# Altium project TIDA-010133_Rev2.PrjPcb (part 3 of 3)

## Sheet 5_BUF802_PWR_PG1.SchDoc: 5_BUF802_PWR
size 431 x 279 mm; Date: Not shown in title block; ApprovedBy: Not shown in title block; CheckedBy: Not shown in title block; Author: Not shown in title block; CompanyName: Not shown in title block; DrawnBy: Rob Stoneham; Engineer: Not shown in title block; Organization: Not shown in title block; Address1: Not shown in title block; Address2: Not shown in title block; Address3: Not shown in title block; Address4: Not shown in title block; DocumentNumber: 6; Revision: Use project parameter SCH_Rev; SheetNumber: 6; SheetTotal: 8; PageSetup: Record=PageOptions¦CenterHorizontal=True¦CenterVertical=True¦PrintScale=1.00¦XCorrection=1.00¦YCorrection=1.00¦PrintKind=0¦BorderSize=5000000¦LeftOffset=0¦BottomOffset=0¦Orientation=2¦PaperLength=1000¦PaperWidth=1000¦Scale=100¦PaperSource=15¦PrintQuality=600¦MediaType=1¦DitherType=10¦PaperKind=Letter¦PrintScaleMode=1
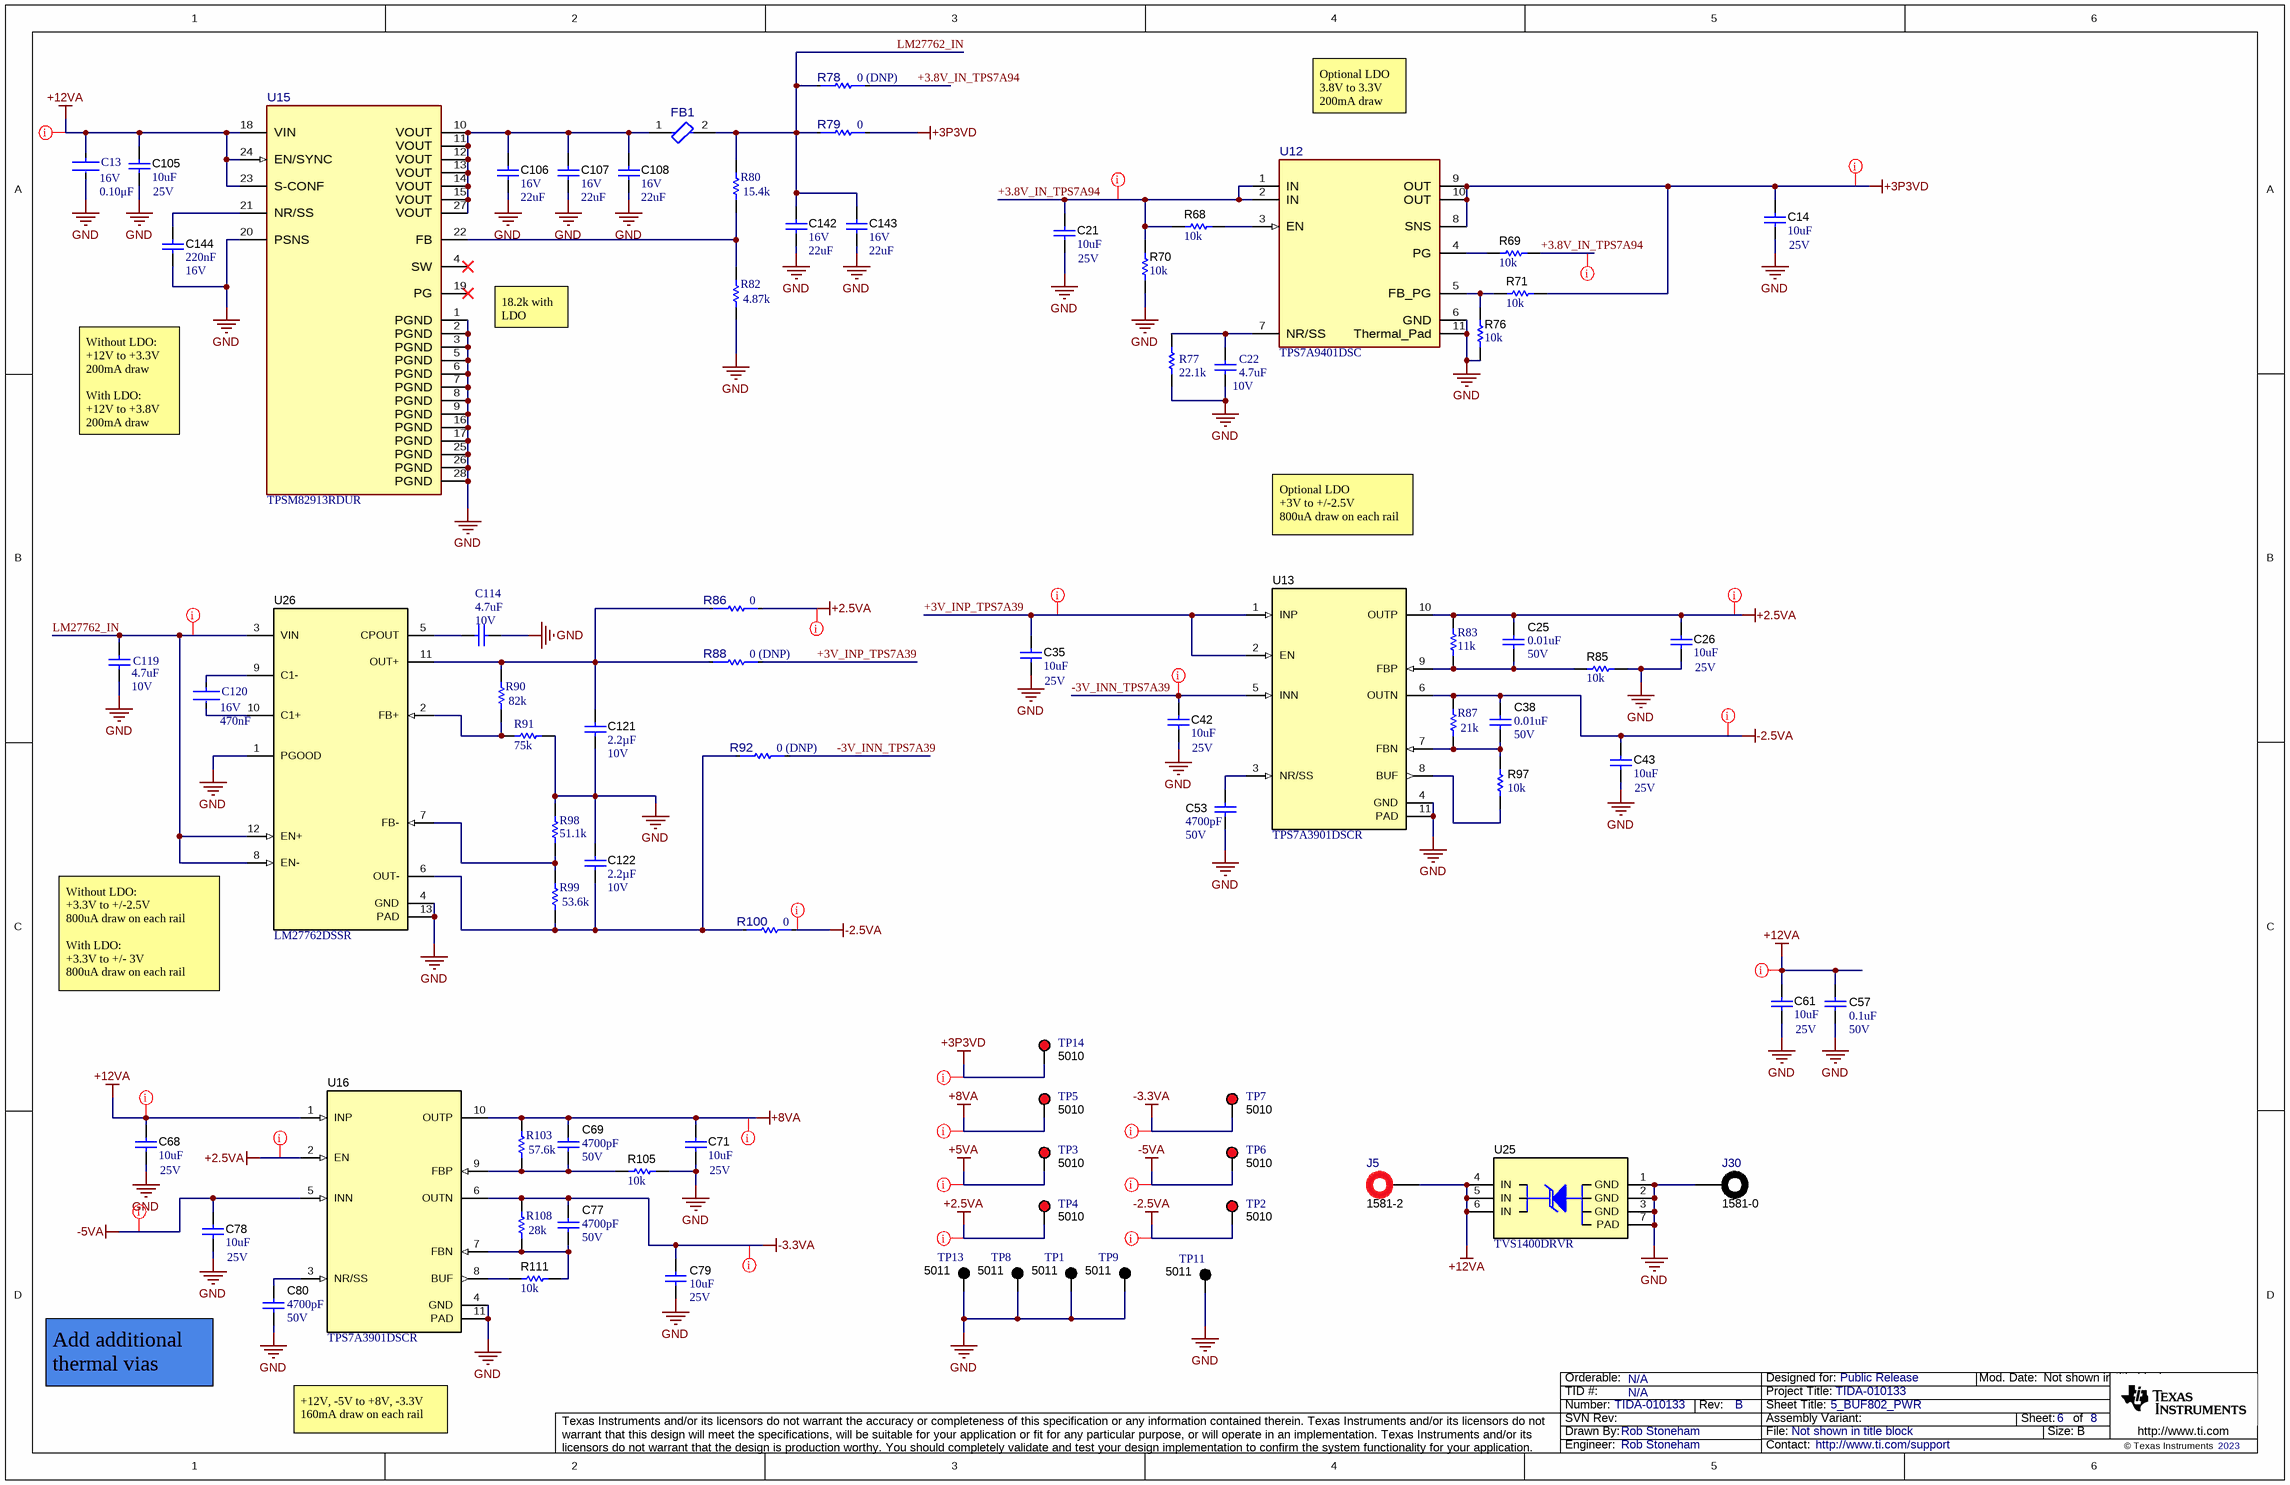
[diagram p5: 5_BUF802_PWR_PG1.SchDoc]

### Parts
C13  Voltage Rating: 16V  Capacitance: 0.10μF  [FP-GRM15-MFG]  (hidden comment: GRM155R71C104KA88D)
C14  ValueDisplayed: 10uF  Value2: 25V  [1206_190]  (hidden comment: C3216X7R1E106M160AE)
C21  ValueDisplayed: 10uF  Value2: 25V  [1206_190]  (hidden comment: C3216X7R1E106M160AE)
C22  value 4.7uF  Voltage Rating: 10V  [CAPC1608X87X35NL15T15]  (hidden comment: C0603C475K8PACTU)
C25  VDC_V: 50V  ValueDisplayed: 0.01uF  [0402]  (hidden comment: GRM155R71H103KA88D)
C26  ValueDisplayed: 10uF  Value2: 25V  [1206_190]  (hidden comment: C3216X7R1E106M160AE)
C35  ValueDisplayed: 10uF  Value2: 25V  [1206_190]  (hidden comment: C3216X7R1E106M160AE)
C38  VDC_V: 50V  ValueDisplayed: 0.01uF  [0402]  (hidden comment: GRM155R71H103KA88D)
C42  ValueDisplayed: 10uF  Value2: 25V  [1206_190]  (hidden comment: C3216X7R1E106M160AE)
C43  ValueDisplayed: 10uF  Value2: 25V  [1206_190]  (hidden comment: C3216X7R1E106M160AE)
C53  value 4700pF  VDC_V: 50V  [0603]  (hidden comment: 885012206087)
C57  ValueDisplayed: 0.1uF  Value2: 50V  [0603]  (hidden comment: CGA3E2X7R1H104K080AA)
C61  ValueDisplayed: 10uF  Value2: 25V  [1206_190]  (hidden comment: C3216X7R1E106M160AE)
C68  ValueDisplayed: 10uF  Value2: 25V  [1206_190]  (hidden comment: C3216X7R1E106M160AE)
C69  value 4700pF  VDC_V: 50V  [0603]  (hidden comment: 885012206087)
C71  ValueDisplayed: 10uF  Value2: 25V  [1206_190]  (hidden comment: C3216X7R1E106M160AE)
C77  value 4700pF  VDC_V: 50V  [0603]  (hidden comment: 885012206087)
C78  ValueDisplayed: 10uF  Value2: 25V  [1206_190]  (hidden comment: C3216X7R1E106M160AE)
C79  ValueDisplayed: 10uF  Value2: 25V  [1206_190]  (hidden comment: C3216X7R1E106M160AE)
C80  value 4700pF  VDC_V: 50V  [0603]  (hidden comment: 885012206087)
C105  ValueDisplayed: 10uF  Value2: 25V  [1206_190]  (hidden comment: C3216X7R1E106M160AE)
C106  VDC_V: 16V  ValueDisplayed: 22uF  [0805_HV]  (hidden comment: C2012X5R1C226K125AC)
C107  VDC_V: 16V  ValueDisplayed: 22uF  [0805_HV]  (hidden comment: C2012X5R1C226K125AC)
C108  VDC_V: 16V  ValueDisplayed: 22uF  [0805_HV]  (hidden comment: C2012X5R1C226K125AC)
C114  value 4.7uF  Voltage Rating: 10V  [CAPC1608X87X35NL15T15]  (hidden comment: C0603C475K8PACTU)
C119  value 4.7uF  Voltage Rating: 10V  [CAPC1608X87X35NL15T15]  (hidden comment: C0603C475K8PACTU)
C120  Voltage Rating (DC): 16V  Capacitance: 470nF  [FP-C1608-080-0_1-MFG]  (hidden comment: C1608X5R1C474K080AA)
C121  Cap_F: 2.2µF  VDC_V: 10V  [0603]  (hidden comment: C1608X7R1A225K080AC)
C122  Cap_F: 2.2µF  VDC_V: 10V  [0603]  (hidden comment: C1608X7R1A225K080AC)
C142  VDC_V: 16V  ValueDisplayed: 22uF  [0805_HV]  (hidden comment: C2012X5R1C226K125AC)
C143  VDC_V: 16V  ValueDisplayed: 22uF  [0805_HV]  (hidden comment: C2012X5R1C226K125AC)
C144  Cap_F: 220nF  VDC_V: 16V  [0603]  (hidden comment: GRM188R71C224KA01D)
FB1  BLE18PS080SN1D  [FP-BLE18PS080SN1D_0603-IPC_B]  (value not drawn)
J5  1581-2  [Pomona_1581-2]
J30  1581-0  [Pomona_1581-0]
R68  ValueDisplayed: 10k  [0603]  (hidden comment: CRCW060310K0JNEA)
R69  ValueDisplayed: 10k  [0603]  (hidden comment: CRCW060310K0JNEA)
R70  ValueDisplayed: 10k  [0603]  (hidden comment: CRCW060310K0JNEA)
R71  ValueDisplayed: 10k  [0603]  (hidden comment: CRCW060310K0JNEA)
R76  ValueDisplayed: 10k  [0603]  (hidden comment: CRCW060310K0JNEA)
R77  value 22.1k  [RESC1609X50X30LL10T20]  (hidden comment: CRCW060322K1FKEA)
R78  value 0 (DNP)  [FP-CRCW04020000Z0EDHP_0402-MFG]  (hidden comment: CRCW04020000Z0EDHP)
R79  value 0  [FP-CRCW04020000Z0EDHP_0402-MFG]  (hidden comment: CRCW04020000Z0EDHP)
R80  value 15.4k  [RESC1609X50X30LL10T20]  (hidden comment: CRCW060315K4FKEA)
R82  value 4.87k  [RESC1608X55X30ML15T15]  (hidden comment: ERJ-3EKF4871V)
R83  value 11k  [RESC1609X50X30ML10T20]  (hidden comment: CRCW060311K0FKEA)
R85  ValueDisplayed: 10k  [0603]  (hidden comment: CRCW060310K0JNEA)
R86  value 0  [FP-CRCW04020000Z0EDHP_0402-MFG]  (hidden comment: CRCW04020000Z0EDHP)
R87  value 21k  [RESC1609X50X30LL10T20]  (hidden comment: CRCW060321K0FKEA)
R88  value 0 (DNP)  [FP-CRCW04020000Z0EDHP_0402-MFG]  (hidden comment: CRCW04020000Z0EDHP)
R90  value 82k  [RESC1608X55X30LL15T15]  (hidden comment: ERJ3EKF8202V)
R91  value 75k  [RESC1609X50X30NL10T20]  (hidden comment: CRCW060375K0FKEA)
R92  value 0 (DNP)  [FP-CRCW04020000Z0EDHP_0402-MFG]  (hidden comment: CRCW04020000Z0EDHP)
R97  ValueDisplayed: 10k  [0603]  (hidden comment: CRCW060310K0JNEA)
R98  value 51.1k  [RESC1609X50X30ML10T20]  (hidden comment: CRCW060351K1FKEA)
R99  value 53.6k  [RESC1608X55X30NL15T15]  (hidden comment: ERJ-3EKF5362V)
R100  value 0  [FP-CRCW04020000Z0EDHP_0402-MFG]  (hidden comment: CRCW04020000Z0EDHP)
R103  value 57.6k  [RESC1608X55X30ML15T15]  (hidden comment: ERJ-3EKF5762V)
R105  ValueDisplayed: 10k  [0603]  (hidden comment: CRCW060310K0JNEA)
R108  value 28k  [RESC1608X55X30LL15T15]  (hidden comment: ERJ-3EKF2802V)
R111  ValueDisplayed: 10k  [0603]  (hidden comment: CRCW060310K0JNEA)
TP1  5011  [Keystone5011]
TP2  5010  [Keystone5010]
TP3  5010  [Keystone5010]
TP4  5010  [Keystone5010]
TP5  5010  [Keystone5010]
TP6  5010  [Keystone5010]
TP7  5010  [Keystone5010]
TP8  5011  [Keystone5011]
TP9  5011  [Keystone5011]
TP11  5011  [Keystone5011]
TP13  5011  [Keystone5011]
TP14  5010  [Keystone5010]
U12  TPS7A9401DSC  [DSC0010J-MFG]
U13  TPS7A3901DSCR  [DSC0010J]
U15  TPSM82913RDUR  [RDU0028A-MFG]
U16  TPS7A3901DSCR  [DSC0010J]
U25  TVS1400DRVR  [DRV0006A]
U26  LM27762DSSR  [DSS0012B]

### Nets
+2.5VA: C25.1 C26.1 R83.2 R86.2 TP4.1 U13.10(OUTP) U16.2(EN)
+3P3VD: C14.1 R71.1 R79.2 TP14.1 U12.8(SNS) U12.9(OUT) U12.10(OUT)
+5VA: TP3.1
+8VA: C69.1 C71.1 R103.2 TP5.1 U16.10(OUTP)
+12VA: C13.2 C57.1 C61.1 C68.1 C105.1 J5.1 U15.18(VIN) U15.23(S-CONF) U15.24(EN/SYNC) U16.1(INP) U25.4(IN) U25.5(IN) U25.6(IN)
-2.5VA: C38.1 C43.1 R87.2 R100.2 TP2.1 U13.6(OUTN)
-3.3VA: C77.1 C79.1 R108.2 TP7.1 U16.6(OUTN)
-5VA: C78.1 TP6.1 U16.5(INN)
GND: C13.1 C14.2 C21.2 C22.1 C26.2 C35.2 C42.2 C43.2 C53.2 C57.2 C61.2 C68.2 C71.2 C78.2 C79.2 C80.2 C105.2 C106.2 C107.2 C108.2 C114.1 C119.1 C121.2 C122.1 C142.2 C143.2 C144.2 J30.1 R70.1 R76.1 R77.1 R82.1 R85.1 R91.1 R98.2 R105.1 TP1.1 TP8.1 TP9.1 TP11.1 TP13.1 U12.6(GND) U12.11(Thermal_Pad) U13.4(GND) U13.11(PAD) U15.1(PGND) U15.2(PGND) U15.3(PGND) U15.5(PGND) U15.6(PGND) U15.7(PGND) U15.8(PGND) U15.9(PGND) U15.16(PGND) U15.17(PGND) U15.20(PSNS) U15.25(PGND) U15.26(PGND) U15.28(PGND) U16.4(GND) U16.11(PAD) U25.1(GND) U25.2(GND) U25.3(GND) U25.7(PAD) U26.1(PGOOD) U26.4(GND) U26.13(PAD)
+3.8V_IN_TPS7A94: C21.1 R68.1 R69.1 R70.2 R78.2 U12.1(IN) U12.2(IN)
+3V_INP_TPS7A39: C35.1 R88.2 U13.1(INP) U13.2(EN)
-3V_INN_TPS7A39: C42.1 R92.2 U13.5(INN)
LM27762_IN: C119.2 C142.1 C143.1 FB1.2 R78.1 R79.1 R80.2 U26.3(VIN) U26.8(EN-) U26.12(EN+)
NetC22_2: C22.2 R77.2 U12.7(NR/SS)
NetC25_2: C25.2 R83.1 R85.2 U13.9(FBP)
NetC38_2: C38.2 R87.1 R97.2 U13.7(FBN)
NetC53_1: C53.1 U13.3(NR/SS)
NetC69_2: C69.2 R103.1 R105.2 U16.9(FBP)
NetC77_2: C77.2 R108.1 R111.1 U16.7(FBN)
NetC80_1: C80.1 U16.3(NR/SS)
NetC106_1: C106.1 C107.1 C108.1 FB1.1 U15.10(VOUT) U15.11(VOUT) U15.12(VOUT) U15.13(VOUT) U15.14(VOUT) U15.15(VOUT) U15.27(VOUT)
NetC114_2: C114.2 U26.5(CPOUT)
NetC120_1: C120.1 U26.10(C1+)
NetC120_2: C120.2 U26.9(C1-)
NetC121_1: C121.1 R86.1 R88.1 R90.2 U26.11(OUT+)
NetC122_2: C122.2 R92.1 R99.1 R100.1 U26.6(OUT-)
NetC144_1: C144.1 U15.21(NR/SS)
NetR68_2: R68.2 U12.3(EN)
NetR69_2: R69.2 U12.4(PG)
NetR71_2: R71.2 R76.2 U12.5(FB_PG)
NetR80_1: R80.1 R82.2 U15.22(FB)
NetR90_1: R90.1 R91.2 U26.2(FB+)
NetR97_1: R97.1 U13.8(BUF)
NetR98_1: R98.1 R99.2 U26.7(FB-)
NetR111_2: R111.2 U16.8(BUF)

Not connected (* = marked no-connect by the designer): U15 4(SW)* 19(PG)*

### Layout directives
net class Power: +2.5VA, +3.8V_IN_TPS7A94, +3P3VD, +3V_INP_TPS7A39, +5VA, +8VA, +12VA, -2.5VA, -3.3VA, -3V_INN_TPS7A39, -5VA, LM27762_IN

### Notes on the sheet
- Optional LDO
  3.8V to 3.3V
  200mA draw
- 18.2k with LDO
- Without LDO:
  +12V to +3.3V
  200mA draw
  With LDO:
  +12V to +3.8V
  200mA draw
- Optional LDO
  +3V to +/-2.5V
  800uA draw on each rail
- Without LDO:
  +3.3V to +/-2.5V
  800uA draw on each rail
  With LDO:
  +3.3V to +/- 3V
  800uA draw on each rail
- Add additional thermal vias
- +12V, -5V to +8V, -3.3V
  160mA draw on each rail

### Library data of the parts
C13 = CMP-2100-03641-2: CAP CER 0.1UF 16V X7R 0402; Manufacturer: Murata; Standoff Height: 0mm; Tolerance: 10%; Material: Ceramic; Value: 0.10μF
C14 C21 C26 C35 C42 C43 C61 C68 C71 C78 C79 C105 = CMP-0008692-2: CAP, CERM, 10 uF, 25 V, +/- 20%, X7R, 1206_190; Manufacturer: TDK; Polarized: N; Value: 10uF; U/M: EA; Cap_F: 10µF; Value1: Unknown; TaMin_C: -55°C; TaMax_C: 125°C; Cap_Case: 1206; SizeArea_mm2: 5.12; SizeAreaWB_mm2: 10.92; SizeX_mm: 3.2; SizeY_mm: 1.6; SizeZ_mm: 1.9; AEC Category: Q200
C22 C114 C119 = CMP-2006-03238-1: CAP, CERM, 4.7uF, 10V, +/-10%, X5R, 0603; Manufacturer: Kemet
C25 C38 = CMP-0006674-2: CAP, CERM, 0.01 uF, 50 V, +/- 10%, X7R, 0402; Manufacturer: MuRata; TaMin_C: -55°C; Polarized: N; SizeAreaWB_mm2: 3; Value1: Unknown; U/M: EA; Value: 0.01uF; TaMax_C: 125°C; SizeZ_mm: 0.6; SizeX_mm: 1; SizeY_mm: 0.5; Cap_F: 10nF; AEC Category: Q200
C53 C69 C77 C80 = CMP-0006835-4: CAP, CERM, 4700 pF, 50 V, +/- 10%, X7R, 0603; Manufacturer: Wurth Elektronik; TaMin_C: -55°C; Polarized: N; SizeAreaWB_mm2: 4.68; Value1: Unknown; U/M: EA; TaMax_C: 125°C; SizeZ_mm: 1; SizeX_mm: 1.6; SizeY_mm: 0.8; SizeArea_mm2: 1.28; Cap_F: 4.7nF; AEC Category: Q200
C57 = CMP-0007078-4: CAP, CERM, 0.1 uF, 50 V, +/- 10%, X7R, AEC-Q200 Grade 1, 0603; Manufacturer: TDK; Polarized: N; Value: 0.1uF; U/M: EA; Cap_F: 100nF; ESR_ohm: 29.6m; Value1: 0.0296 ohm; IRMS_A: 971.99mA; TaMin_C: -55°C; TaMax_C: 125°C; SizeArea_mm2: 1.28; SizeAreaWB_mm2: 4.68; SizeX_mm: 1.6; SizeY_mm: 0.8; SizeZ_mm: 1; AEC Category: Q200; AEC Qualified: Y
C106-C108 C142 C143 = CMP-0007826-2: CAP, CERM, 22 uF, 16 V, +/- 10%, X5R, 0805; Manufacturer: TDK; TaMin_C: -55°C; Polarized: N; SizeAreaWB_mm2: 6.75; Value1: Unknown; U/M: EA; Value: 22uF; TaMax_C: 85°C; SizeZ_mm: 1.45; SizeX_mm: 2; SizeY_mm: 1.25; Cap_Case: 0805; SizeArea_mm2: 2.5; Cap_F: 22µF; AEC Category: Q200
C120 = CMP-08246-005464-1: Multilayer Ceramic Capacitors 470nF ±10% 16V X5R SMD 0603
C121 C122 = CMP-0007036-4: CAP, CERM, 2.2 uF, 10 V, +/- 10%, X7R, 0603; Manufacturer: TDK; TaMin_C: -55°C; ESR_ohm: 4.058m; Polarized: N; SizeAreaWB_mm2: 4.68; Value1: 0.004058 ohm; U/M: EA; Value: 2.2uF; TaMax_C: 125°C; SizeZ_mm: 1; SizeX_mm: 1.6; SizeY_mm: 0.8; SizeArea_mm2: 1.28; IRMS_A: 2.5827A; AEC Category: Q200
C144 = CMP-0007389-4: CAP, CERM, 0.22 uF, 16 V, +/- 10%, X7R, 0603; Manufacturer: MuRata; TaMin_C: -55°C; Polarized: N; SizeAreaWB_mm2: 4.68; Value1: Unknown; U/M: EA; Value: 0.22uF; TaMax_C: 125°C; SizeZ_mm: 1; SizeX_mm: 1.6; SizeY_mm: 0.8; SizeArea_mm2: 1.28; AEC Category: Q200
FB1 = CMP-0096943-2: Ferrite Chip Bead 8A 8.5Ohm 2-Pin 0603 Paper T/R; Manufacturer: Murata; AEC Qualified: No; Impedance At Frequency: 8.5Ω @ 100MHz; DCR_ohm: 4m; Test Frequency: 100MHz; Tolerance_%: 25%; SizeZ_mm: 0.75mm
J5 = CMP-0082515-1: Banana Jack Red, TH; Manufacturer: Pomona Electronics; ContactFinish: Tin; Gender: Female; Current_A: 15A
J30 = CMP-0082516-1: Banana Jack Black, TH; Manufacturer: Pomona Electronics; Gender: Female; Current_A: 15A; ContactFinish: Tin
R68-R71 R76 R85 R97 R105 R111 = CMP-0025701-4: RES, 10 k, 5%, 0.1 W, AEC-Q200 Grade 0, 0603; Manufacturer: Vishay-Dale; Value: 10k; Value_Code: 10k0; Power_W: 100mW; Value2: 0.1W; VDC_V: 75V; TempCo: 200 ppm/C; SizeArea_mm2: 1.28; SizeX_mm: 1.6; SizeY_mm: 0.8; SizeZ_mm: 1; EIA_Code: E24; AEC Category: Q200; AEC Qualified: Y; AEC Grade: 0
R77 = CMP-2000-03094-1: RES 22.1K, 1%, 0.1W, 0603; Manufacturer: Vishay Dale
R78 R88 R92 = CMP-0001606-2: RES Thick Film, 0Ω, 0.2W, 0402; Manufacturer: Vishay Dale; AEC Qualified: Yes; Res_ohm: 0; SizeZ_mm: 0.4mm; AEC Grade: Grade 0; Power_W: 200mW; VDC_V: 50V
R79 R86 R100 = CMP-0001606-2: RES Thick Film, 0Ω, 0.2W, 0402; Manufacturer: Vishay Dale; AEC Qualified: Yes; SizeZ_mm: 0.4mm; AEC Grade: Grade 0; Power_W: 200mW; VDC_V: 50V
R80 = CMP-2000-02924-1: RES 15.4K, 1%, 0.1W, 0603; Manufacturer: Vishay Dale
R82 = CMP-2000-00532-1: RES, 4.87k, 1%, 0.1W, 0603; Manufacturer: Panasonic
R83 = CMP-2000-03860-1: RES 11k, 1%, 0.1W, 0603; Manufacturer: Vishay Dale
R87 = CMP-2000-03080-1: RES 21k, 1%, 0.1W, 0603; Manufacturer: Vishay Dale
R90 = CMP-2000-00656-1: RES 82k, 1%, 0.1W, 0603; Manufacturer: Panasonic
R91 = CMP-2000-03571-1: RES 75k, 1%, 0.1W, 0603; Manufacturer: Vishay Dale
R98 = CMP-2000-03445-1: 51.1 kOhms ±1% 0.1W, 1/10W Chip Resistor 0603 (1608 Metric) Automotive AEC-Q200 Thick Film; Manufacturer: Vishay Dale
R99 = CMP-2000-00556-1: 53.6 kOhms ±1% 0.1W, 1/10W Chip Resistor 0603 (1608 Metric) Automotive AEC-Q200 Thick Film; Manufacturer: Panasonic
R103 = CMP-2000-00576-1: 57.6 kOhms ±1% 0.1W, 1/10W Chip Resistor 0603 (1608 Metric) Automotive AEC-Q200 Thick Film; Manufacturer: Panasonic
R108 = CMP-1012-00672-2: 28 kOhms ±1% 0.1W, 1/10W Chip Resistor 0603 (1608 Metric) Automotive AEC-Q200 Thick Film; Manufacturer: Panasonic
TP1 TP8 TP9 TP11 TP13 = CMP-0055148-2: Test Point, Multipurpose, Black, TH; Manufacturer: Keystone Electronics; CNHeader: FALSE; Green_Lifecycle: Active; Green_REACh: Passed; ContactFinish: Silver; CT: TRUE
TP2-TP7 TP14 = CMP-0055147-2: Test Point, Multipurpose, Red, TH; Manufacturer: Keystone Electronics; CNHeader: FALSE; Green_Lifecycle: Active; Green_REACh: Passed; ContactFinish: Silver; CT: TRUE
U12 = CMP-0091022-1: 1-A, Ultra-Low Noise, Ultra-High PSRR, RF Voltage Regulator; Manufacturer: Texas Instruments; Max Supply Voltage: 5.5V; Accuracy Percentage: 1-1.5%; SizeZ_mm: 0.8mm; Output Type: AdjustableProgrammable; Min Supply Voltage: 1.7V; TJmax_C: +150°C; Dropout Voltage: 210mV; AEC Qualified: No; Standoff Height: 0mm; Output Voltage: 0.4-5.3V; Number Of Outputs: 1; Nominal Supply Current: 15-47mA
U13 U16 = CMP-0013435-7: Dual, 150mA, Wide-Vin, Positive and Negative Low-Dropout (LDO) Voltage Regulator, DSC0010J (WSON-10); Alternate Manufacturer: Texas Instruments; Alternate PartNumber: TPS7A3901DSCT; Rating: Catalog; CompType: IC; SizeAreaWB_mm2: 16.0; SizeY_mm: 3.0; AEC Qualified: N; SizeZ_mm: 0.8; SizeArea_mm2: 9.0; AEC Category: Q200
U15 = CMP-0094707-3: 3-V to 17-V, 3-A Low Noise and Low Ripple Buck Converter Module with Integrated Ferrite Bead Filter Compensation; Manufacturer: Texas Instruments; Switching Frequency: 1/2.2MHz; Max Duty Cycle: 100%; Output Voltage: 0.8-5.5V; Standoff Height: 0mm; CompType: IC; Number Of Outputs: 1; Max Supply Voltage: 17V; AEC Category: Q200; TJmax_C: +125°C; Nominal Supply Current: 5mA; SizeZ_mm: 1.9mm; Output Type: AdjustableProgrammable; Min Supply Voltage: 3V; AEC Qualified: No
U25 = CMP-0077836-1: 14-V Precision Surge Protection Clamp, DRV0006A (WSON-6); Alternate Manufacturer: Texas Instruments; SizeAreaWB_mm2: 9.0; SizeZ_mm: 0.8; SizeX_mm: 2.0; SizeArea_mm2: 4.0; CompType: IC; AEC Qualified: N; AEC Category: Q200
U26 = CMP-0076280-3: Low-Noise Positive- and Negative-Output Charge Pump With Integrated LDO, DSS0012B (WSON-12); Alternate PartNumber: LM27762DSST; Alternate Manufacturer: Texas Instruments; SizeZ_mm: 0.8; SizeArea_mm2: 6.0; AEC Qualified: N; Rating: Catalog; SizeY_mm: 3.0; SizeX_mm: 2.0; CompType: IC; AEC Category: Q200; SizeAreaWB_mm2: 12.0

## Sheet 6_BUF802_PWR_PG2.SchDoc
size 431 x 279 mm; Date: Not shown in title block; ApprovedBy: Not shown in title block; CheckedBy: Not shown in title block; Author: Not shown in title block; CompanyName: Not shown in title block; Engineer: Not shown in title block; Organization: Not shown in title block; Address1: Not shown in title block; Address2: Not shown in title block; Address3: Not shown in title block; Address4: Not shown in title block; DocumentNumber: 7; Revision: Use project parameter SCH_Rev; SheetNumber: 7; SheetTotal: 8; PageSetup: Record=PageOptions¦CenterHorizontal=True¦CenterVertical=True¦PrintScale=1.00¦XCorrection=1.00¦YCorrection=1.00¦PrintKind=0¦BorderSize=5000000¦LeftOffset=0¦BottomOffset=0¦Orientation=2¦PaperLength=1000¦PaperWidth=1000¦Scale=100¦PaperSource=15¦PrintQuality=600¦MediaType=1¦DitherType=10¦PaperKind=Letter¦PrintScaleMode=1
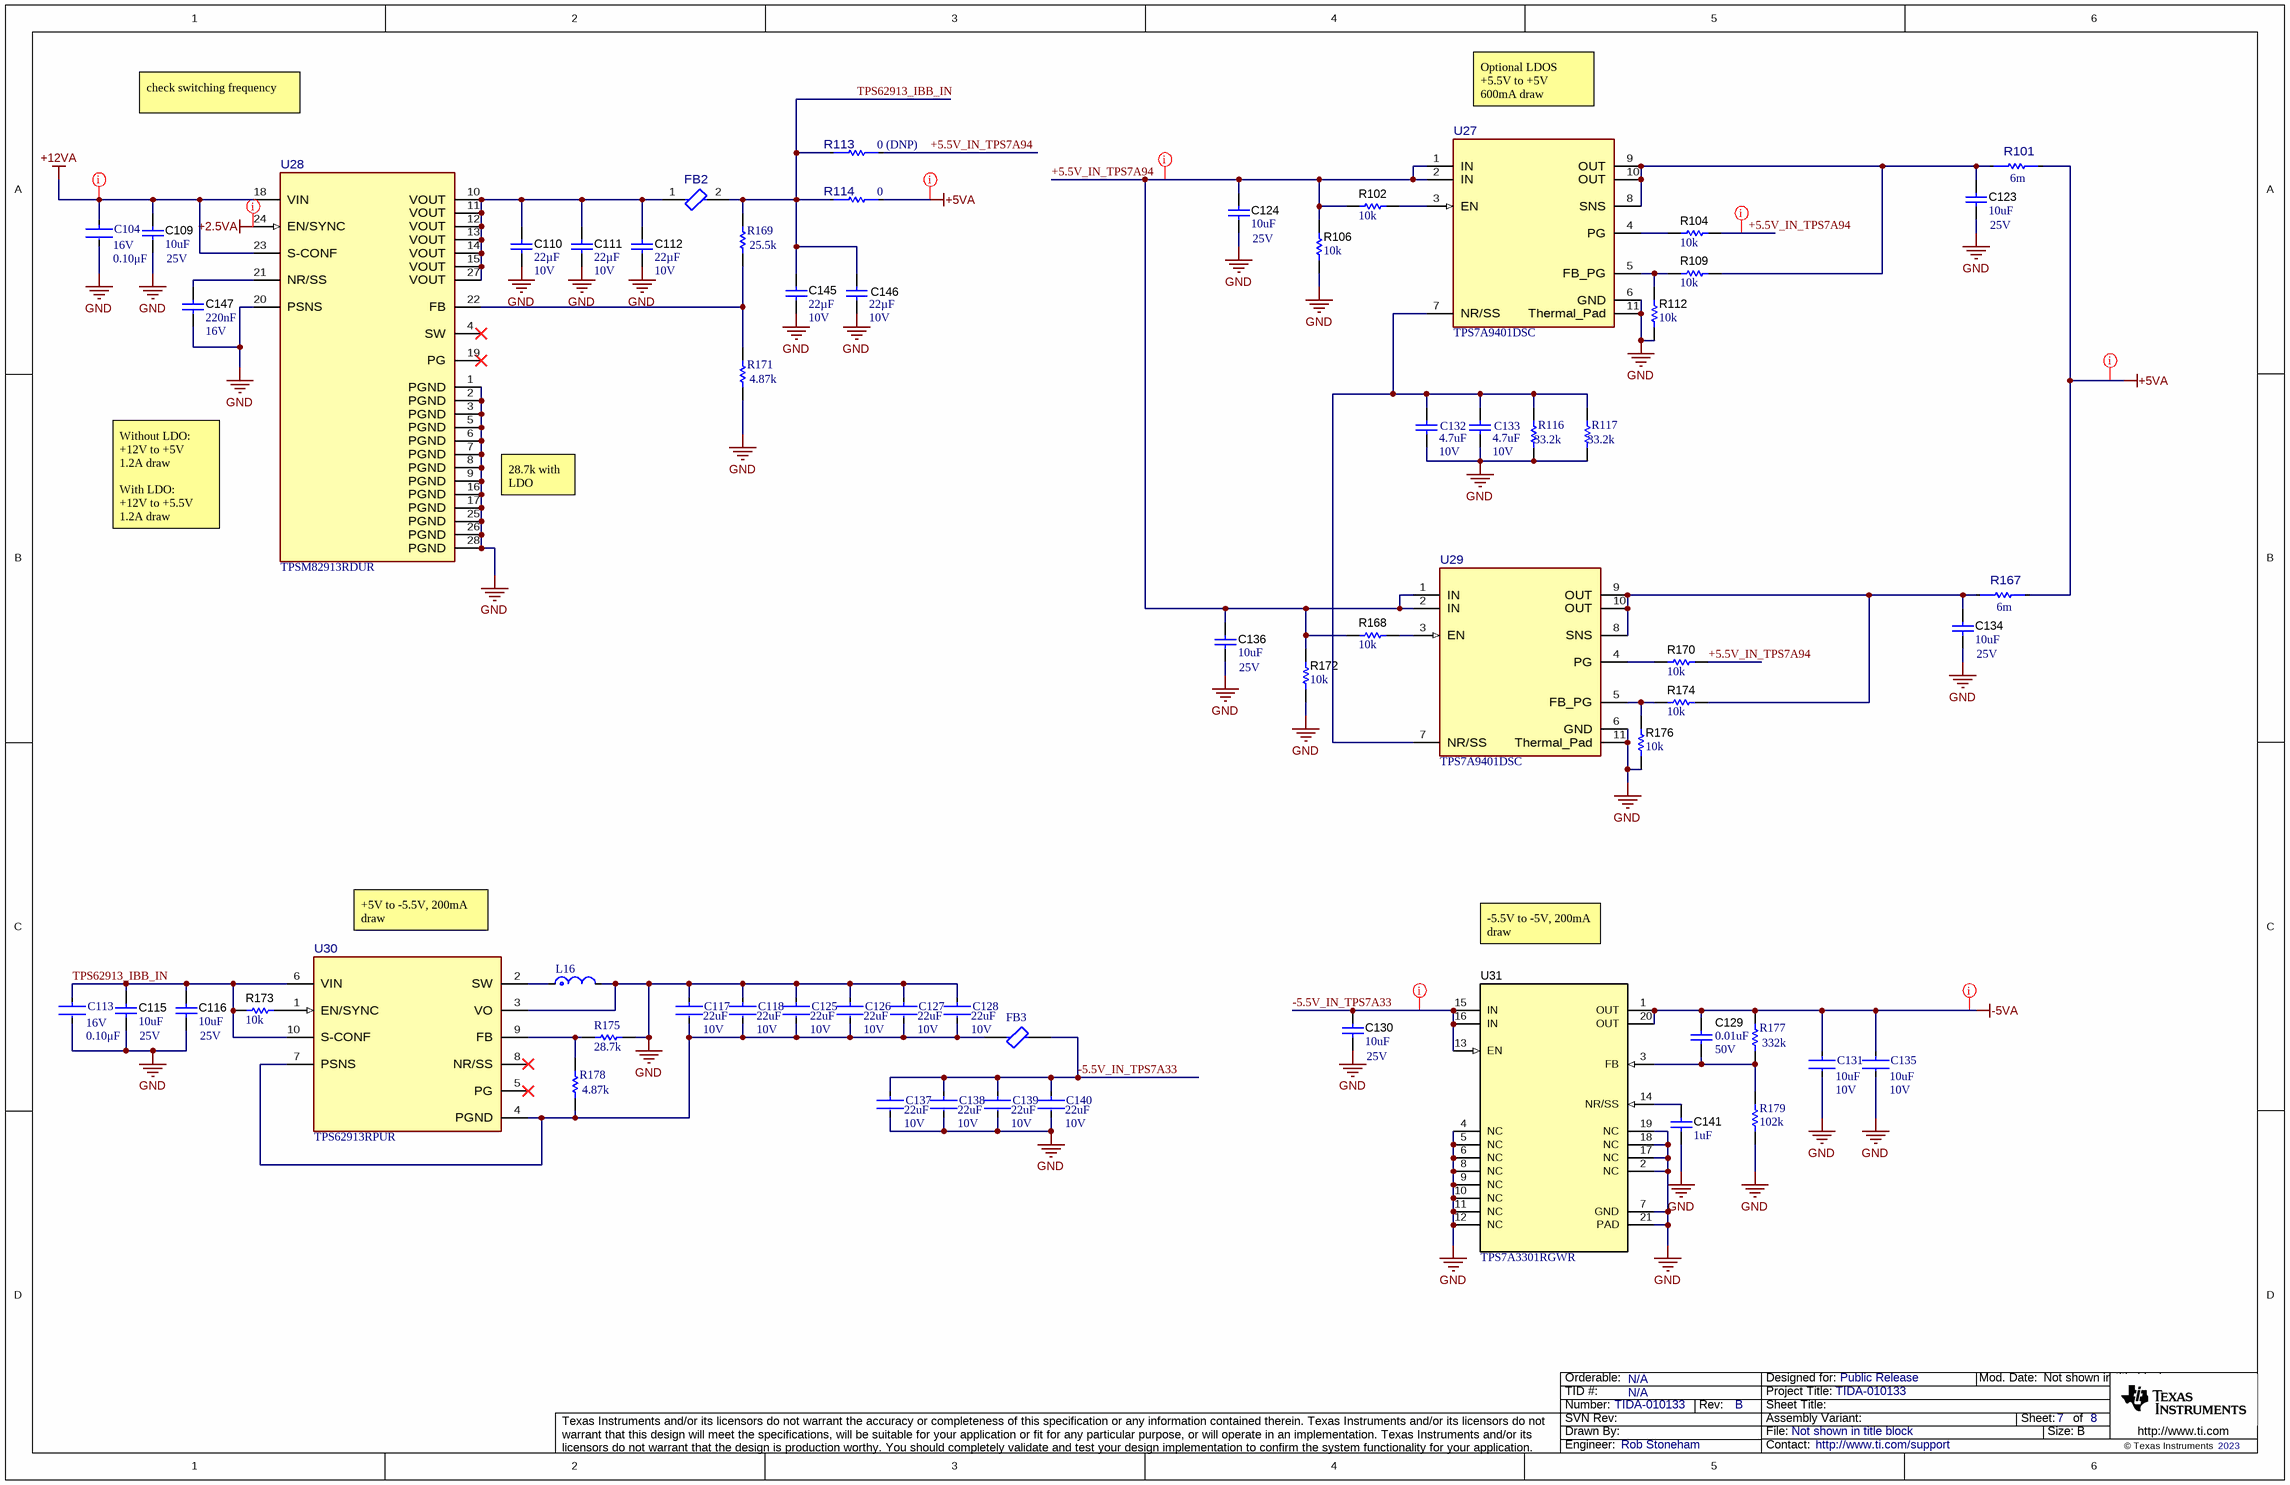
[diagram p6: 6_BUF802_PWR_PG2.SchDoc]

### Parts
C104  Voltage Rating: 16V  Capacitance: 0.10μF  [FP-GRM15-MFG]  (hidden comment: GRM155R71C104KA88D)
C109  ValueDisplayed: 10uF  Value2: 25V  [1206_190]  (hidden comment: C3216X7R1E106M160AE)
C110  ValueDisplayed: 22µF  VDC_V: 10V  [0805_HV]  (hidden comment: GRM21BD71A226ME44L)
C111  ValueDisplayed: 22µF  VDC_V: 10V  [0805_HV]  (hidden comment: GRM21BD71A226ME44L)
C112  ValueDisplayed: 22µF  VDC_V: 10V  [0805_HV]  (hidden comment: GRM21BD71A226ME44L)
C113  Voltage Rating: 16V  Capacitance: 0.10μF  [FP-GRM15-MFG]  (hidden comment: GRM155R71C104KA88D)
C115  ValueDisplayed: 10uF  Value2: 25V  [1206_190]  (hidden comment: C3216X7R1E106M160AE)
C116  ValueDisplayed: 10uF  Value2: 25V  [1206_190]  (hidden comment: C3216X7R1E106M160AE)
C117  Voltage Rating: 10V  Capacitance: 22uF  [FP-GRM31C-0_2-e0_3_0_8-MFG]  (hidden comment: GRM31CR71A226KE15L)
C118  Voltage Rating: 10V  Capacitance: 22uF  [FP-GRM31C-0_2-e0_3_0_8-MFG]  (hidden comment: GRM31CR71A226KE15L)
C123  ValueDisplayed: 10uF  Value2: 25V  [1206_190]  (hidden comment: C3216X7R1E106M160AE)
C124  ValueDisplayed: 10uF  Value2: 25V  [1206_190]  (hidden comment: C3216X7R1E106M160AE)
C125  Voltage Rating: 10V  Capacitance: 22uF  [FP-GRM31C-0_2-e0_3_0_8-MFG]  (hidden comment: GRM31CR71A226KE15L)
C126  Voltage Rating: 10V  Capacitance: 22uF  [FP-GRM31C-0_2-e0_3_0_8-MFG]  (hidden comment: GRM31CR71A226KE15L)
C127  Voltage Rating: 10V  Capacitance: 22uF  [FP-GRM31C-0_2-e0_3_0_8-MFG]  (hidden comment: GRM31CR71A226KE15L)
C128  Voltage Rating: 10V  Capacitance: 22uF  [FP-GRM31C-0_2-e0_3_0_8-MFG]  (hidden comment: GRM31CR71A226KE15L)
C129  VDC_V: 50V  ValueDisplayed: 0.01uF  [0402]  (hidden comment: GRM155R71H103KA88D)
C130  ValueDisplayed: 10uF  Value2: 25V  [1206_190]  (hidden comment: C3216X7R1E106M160AE)
C131  Voltage Rating (DC): 10V  Capacitance: 10uF  [FP-C1608-080-0_1-MFG]  (hidden comment: C1608X5R1A106K080AC)
C132  value 4.7uF  Voltage Rating: 10V  [CAPC1608X87X35NL15T15]  (hidden comment: C0603C475K8PACTU)
C133  value 4.7uF  Voltage Rating: 10V  [CAPC1608X87X35NL15T15]  (hidden comment: C0603C475K8PACTU)
C134  ValueDisplayed: 10uF  Value2: 25V  [1206_190]  (hidden comment: C3216X7R1E106M160AE)
C135  Voltage Rating (DC): 10V  Capacitance: 10uF  [FP-C1608-080-0_1-MFG]  (hidden comment: C1608X5R1A106K080AC)
C136  ValueDisplayed: 10uF  Value2: 25V  [1206_190]  (hidden comment: C3216X7R1E106M160AE)
C137  Voltage Rating: 10V  Capacitance: 22uF  [FP-GRM31C-0_2-e0_3_0_8-MFG]  (hidden comment: GRM31CR71A226KE15L)
C138  Voltage Rating: 10V  Capacitance: 22uF  [FP-GRM31C-0_2-e0_3_0_8-MFG]  (hidden comment: GRM31CR71A226KE15L)
C139  Voltage Rating: 10V  Capacitance: 22uF  [FP-GRM31C-0_2-e0_3_0_8-MFG]  (hidden comment: GRM31CR71A226KE15L)
C140  Voltage Rating: 10V  Capacitance: 22uF  [FP-GRM31C-0_2-e0_3_0_8-MFG]  (hidden comment: GRM31CR71A226KE15L)
C141  ValueDisplayed: 1uF  [0603]  (hidden comment: C1608X7R1C105K080AC)
C145  ValueDisplayed: 22µF  VDC_V: 10V  [0805_HV]  (hidden comment: GRM21BD71A226ME44L)
C146  ValueDisplayed: 22µF  VDC_V: 10V  [0805_HV]  (hidden comment: GRM21BD71A226ME44L)
C147  Cap_F: 220nF  VDC_V: 16V  [0603]  (hidden comment: GRM188R71C224KA01D)
FB2  BLE18PS080SN1D  [FP-BLE18PS080SN1D_0603-IPC_B]  (value not drawn)
FB3  BLE18PS080SN1D  [FP-BLE18-0_15-t0_6-IPC_B]  (value not drawn)
L16  XGL4020-222MEC  [FP-XGL4020-MFG]  (value not drawn)
R101  value 6m  [FP-KRL2012E-M-R006-F-T5_0805-MFG]  (hidden comment: KRL2012E-M-R006-F-T5)
R102  ValueDisplayed: 10k  [0603]  (hidden comment: CRCW060310K0JNEA)
R104  ValueDisplayed: 10k  [0603]  (hidden comment: CRCW060310K0JNEA)
R106  ValueDisplayed: 10k  [0603]  (hidden comment: CRCW060310K0JNEA)
R109  ValueDisplayed: 10k  [0603]  (hidden comment: CRCW060310K0JNEA)
R112  ValueDisplayed: 10k  [0603]  (hidden comment: CRCW060310K0JNEA)
R113  value 0 (DNP)  [FP-JR0805X35E_0805-MFG]  (hidden comment: JR0805X35E)
R114  value 0  [FP-JR0805X35E_0805-MFG]  (hidden comment: JR0805X35E)
R116  value 33.2k  [RESC1608X55X30NL15T15]  (hidden comment: ERJ-3EKF3322V)
R117  value 33.2k  [RESC1608X55X30NL15T15]  (hidden comment: ERJ-3EKF3322V)
R167  value 6m  [FP-KRL2012E-M-R006-F-T5_0805-MFG]  (hidden comment: KRL2012E-M-R006-F-T5)
R168  ValueDisplayed: 10k  [0603]  (hidden comment: CRCW060310K0JNEA)
R169  value 25.5k  [RESC1608X55X30LL15T15]  (hidden comment: ERJ-3EKF2552V)
R170  ValueDisplayed: 10k  [0603]  (hidden comment: CRCW060310K0JNEA)
R171  value 4.87k  [RESC1608X55X30ML15T15]  (hidden comment: ERJ-3EKF4871V)
R172  ValueDisplayed: 10k  [0603]  (hidden comment: CRCW060310K0JNEA)
R173  ValueDisplayed: 10k  [0603]  (hidden comment: CRCW060310K0JNEA)
R174  ValueDisplayed: 10k  [0603]  (hidden comment: CRCW060310K0JNEA)
R175  value 28.7k  [RESC1608X55X30ML15T15]  (hidden comment: ERJ-3EKF2872V)
R176  ValueDisplayed: 10k  [0603]  (hidden comment: CRCW060310K0JNEA)
R177  value 332k  [RESC1608X55X30ML15T15]  (hidden comment: ERJ-3EKF3323V)
R178  value 4.87k  [RESC1608X55X30ML15T15]  (hidden comment: ERJ-3EKF4871V)
R179  value 102k  [RESC1608X55X30LL15T15]  (hidden comment: ERJ-3EKF1023V)
U27  TPS7A9401DSC  [DSC0010J-MFG]
U28  TPSM82913RDUR  [RDU0028A-MFG]
U29  TPS7A9401DSC  [DSC0010J-MFG]
U30  TPS62913RPUR  [RPU0010A-MFG]
U31  TPS7A3301RGWR  [RGW0020A]

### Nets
+2.5VA: U28.24(EN/SYNC)
+5VA: R101.2 R114.2 R167.2
+12VA: C104.2 C109.1 U28.18(VIN) U28.23(S-CONF)
-5VA: C129.1 C131.2 C135.2 R177.2 U31.1(OUT) U31.20(OUT)
GND: C104.1 C109.2 C110.2 C111.2 C112.2 C113.1 C115.2 C116.2 C117.1 C118.1 C123.2 C124.2 C125.1 C126.1 C127.1 C128.1 C130.2 C131.1 C132.1 C133.1 C134.2 C135.1 C136.2 C137.2 C138.2 C139.2 C140.2 C141.2 C145.2 C146.2 C147.2 L16.2 R106.1 R112.1 R116.1 R117.1 R171.1 R172.1 R175.1 R176.1 R179.1 U27.6(GND) U27.11(Thermal_Pad) U28.1(PGND) U28.2(PGND) U28.3(PGND) U28.5(PGND) U28.6(PGND) U28.7(PGND) U28.8(PGND) U28.9(PGND) U28.16(PGND) U28.17(PGND) U28.20(PSNS) U28.25(PGND) U28.26(PGND) U28.28(PGND) U29.6(GND) U29.11(Thermal_Pad) U30.3(VO) U31.2(NC) U31.4(NC) U31.5(NC) U31.6(NC) U31.7(GND) U31.8(NC) U31.9(NC) U31.10(NC) U31.11(NC) U31.12(NC) U31.17(NC) U31.18(NC) U31.19(NC) U31.21(PAD)
+5.5V_IN_TPS7A94: C124.1 C136.1 R102.1 R104.1 R106.2 R113.2 R168.1 R170.1 R172.2 U27.1(IN) U27.2(IN) U29.1(IN) U29.2(IN)
-5.5V_IN_TPS7A33: C130.1 C137.1 C138.1 C139.1 C140.1 FB3.2 U31.13(EN) U31.15(IN) U31.16(IN)
TPS62913_IBB_IN: C113.2 C115.1 C116.1 C145.1 C146.1 FB2.2 R113.1 R114.1 R169.2 R173.2 U30.6(VIN) U30.10(S-CONF)
NetC110_1: C110.1 C111.1 C112.1 FB2.1 U28.10(VOUT) U28.11(VOUT) U28.12(VOUT) U28.13(VOUT) U28.14(VOUT) U28.15(VOUT) U28.27(VOUT)
NetC117_2: C117.2 C118.2 C125.2 C126.2 C127.2 C128.2 FB3.1 R178.1 U30.4(PGND) U30.7(PSNS)
NetC123_1: C123.1 R101.1 R109.1 U27.8(SNS) U27.9(OUT) U27.10(OUT)
NetC129_2: C129.2 R177.1 R179.2 U31.3(FB)
NetC132_2: C132.2 C133.2 R116.2 R117.2 U27.7(NR/SS) U29.7(NR/SS)
NetC134_1: C134.1 R167.1 R174.1 U29.8(SNS) U29.9(OUT) U29.10(OUT)
NetC141_1: C141.1 U31.14(NR/SS)
NetC147_1: C147.1 U28.21(NR/SS)
NetL16_1: L16.1 U30.2(SW)
NetR102_2: R102.2 U27.3(EN)
NetR104_2: R104.2 U27.4(PG)
NetR109_2: R109.2 R112.2 U27.5(FB_PG)
NetR168_2: R168.2 U29.3(EN)
NetR169_1: R169.1 R171.2 U28.22(FB)
NetR170_2: R170.2 U29.4(PG)
NetR173_1: R173.1 U30.1(EN/SYNC)
NetR174_2: R174.2 R176.2 U29.5(FB_PG)
NetR175_2: R175.2 R178.2 U30.9(FB)

Not connected (* = marked no-connect by the designer): U28 4(SW)* 19(PG)*; U30 5(PG)* 8(NR/SS)*

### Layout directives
net class Power: +2.5VA, +5.5V_IN_TPS7A94, +5VA, +12VA, -5.5V_IN_TPS7A33, -5VA

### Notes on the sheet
- check switching frequency
- Optional LDOS +5.5V to +5V
  600mA draw
- (near U28) 28.7k with LDO
- Without LDO:
  +12V to +5V
  1.2A draw
  With LDO:
  +12V to +5.5V
  1.2A draw
- +5V to -5.5V, 200mA draw
- -5.5V to -5V, 200mA draw

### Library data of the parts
C104 C113 = CMP-2100-03641-2: as C13 on sheet 5_BUF802_PWR_PG1
C109 C115 C116 C123 C124 C130 C134 C136 = CMP-0008692-2: as C14 on sheet 5_BUF802_PWR_PG1
C110-C112 C145 C146 = CMP-0860494-1: CAP, CERM, 22 µF, 10 V,+/- 20%, X7T, 0805; Manufacturer: MuRata; SizeY_mm: 1.25; TaMin_C: -55°C; Value: 22uF; SizeZ_mm: 1.45; Polarized: N; AEC Category: Q200; U/M: EA; Cap_Case: 0805; SizeX_mm: 2; SizeArea_mm2: 2.5; SizeAreaWB_mm2: 6.75; TaMax_C: 125°C
C117 C118 C125-C128 C137-C140 = CMP-06035-003841-1: Chip Multilayer Ceramic Capacitors for General Purpose, 1206, 22uF, X7R, 15%, 10%, 10V
C129 = CMP-0006674-2: as C25 on sheet 5_BUF802_PWR_PG1
C131 C135 = CMP-2000-04979-3: Multilayer Ceramic Capacitors 10μF ±10% 10V X5R SMD 0603
C132 C133 = CMP-2006-03238-1: as C22 on sheet 5_BUF802_PWR_PG1
C141 = CMP-0007037-4: CAP, CERM, 1 uF, 16 V, +/- 10%, X7R, 0603; Manufacturer: TDK; Polarized: N; Value: 1uF; U/M: EA; Cap_F: 1µF; ESR_ohm: 5.7m; Value1: 0.0057 ohm; VDC_V: 16V; TaMin_C: -55°C; TaMax_C: 125°C; SizeArea_mm2: 1.28; SizeAreaWB_mm2: 4.68; SizeX_mm: 1.6; SizeY_mm: 0.8; SizeZ_mm: 1; AEC Category: Q200
C147 = CMP-0007389-4: as C144 on sheet 5_BUF802_PWR_PG1
FB2 = CMP-0096943-2: as FB1 on sheet 5_BUF802_PWR_PG1
FB3 = CMP-06046-000742-1: Ferrite Chip Bead 8A 8.5Ohm 2-Pin 0603 Paper T/R; Manufacturer: Murata
L16 = CMP-11268-000045-2: Shielded Power Inductors
R101 R167 = CMP-0090334-1: 6 mOhms ±1% 1W Chip Resistor Wide 0805 (2012 Metric), 0508 Automotive AEC-Q200, Current Sense Metal Foil; Manufacturer: Susumu; TempCo: 50ppm/°C; SizeZ_mm: 0.7mm; Power_W: 660mW; AEC Qualified: Yes; AEC Grade: Grade 0
R102 R104 R106 R109 R112 R168 R170 R172-R174 R176 = CMP-0025701-4: as R68-R71 on sheet 5_BUF802_PWR_PG1
R113 = CMP-0096818-1: 0 Ohms Jumper 0.245W Chip Resistor 0805 (2012 Metric) - Metal Element; Manufacturer: Ohmite; Res_ohm: 0; AEC Qualified: No; Power_W: 245mW; SizeZ_mm: 0.55mm
R114 = CMP-0096818-1: 0 Ohms Jumper 0.245W Chip Resistor 0805 (2012 Metric) - Metal Element; Manufacturer: Ohmite; AEC Qualified: No; Power_W: 245mW; SizeZ_mm: 0.55mm
R116 R117 = CMP-2000-00441-1: 33.2 kOhms ±1% 0.1W, 1/10W Chip Resistor 0603 (1608 Metric) Automotive AEC-Q200 Thick Film; Manufacturer: Panasonic
R169 = CMP-1012-00667-2: 25.5 kOhms ±1% 0.1W, 1/10W Chip Resistor 0603 (1608 Metric) Automotive AEC-Q200 Thick Film; Manufacturer: Panasonic
R171 R178 = CMP-2000-00532-1: as R82 on sheet 5_BUF802_PWR_PG1
R175 = CMP-2000-00404-1: 28.7 kOhms ±1% 0.1W, 1/10W Chip Resistor 0603 (1608 Metric) Automotive AEC-Q200 Thick Film; Manufacturer: Panasonic
R177 = CMP-2000-00442-1: 332 kOhms ±1% 0.1W, 1/10W Chip Resistor 0603 (1608 Metric) Automotive AEC-Q200 Thick Film; Manufacturer: Panasonic
R179 = CMP-1012-00737-2: 102 kOhms ±1% 0.1W, 1/10W Chip Resistor 0603 (1608 Metric) Automotive AEC-Q200 Thick Film; Manufacturer: Panasonic
U27 U29 = CMP-0091022-1: as U12 on sheet 5_BUF802_PWR_PG1
U28 = CMP-0094707-3: as U15 on sheet 5_BUF802_PWR_PG1
U30 = CMP-0089785-1: 3V to 17V, 3A Micro Noise (20µVRMS) and Micro Ripple (200µVPP) buck converter; Manufacturer: Texas Instruments; SizeZ_mm: 1mm; TJmax_C: +150°C; Output Type: AdjustableProgrammable; Switching Frequency: 1/2.2MHz; Max Duty Cycle: 55%; Number Of Outputs: 1; Nominal Supply Current: 5mA; AEC Qualified: No; Output Voltage: 0.8-5.5V; Standoff Height: 0mm
U31 = CMP-0036411-3: Vin -3V to -36V, -1A, Ultra-Low-Noise, High-PSRR, Low-Dropout Linear Regulator, RGW0020A (VQFN-20); Manufacturer: Texas Instruments; CompType: IC; Vin(Min)(V): -3; AEC Category: Q200; Accuracy(%): 1.5; Vout Adj(Min)(V): -1.18; SizeY_mm: 5.0; Rating: Catalog; Vin(Max)(V): -36; SizeZ_mm: 1.0; AEC Qualified: N; Vout Adj(Max)(V): -33; Vdo(Typ)(mV): 290; Iq(Typ)(mA): 0.21; Iout(Max)(A): 1; SizeAreaWB_mm2: 49.0; SizeArea_mm2: 25.0

## Sheet EVM_Hardware.SchDoc: EVM_Hardware
size 431 x 279 mm; Date: Not shown in title block; ApprovedBy: Not shown in title block; CheckedBy: Not shown in title block; Author: Not shown in title block; CompanyName: Not shown in title block; DrawnBy: Rob Stoneham; Engineer: Not shown in title block; Organization: Not shown in title block; Address1: Not shown in title block; Address2: Not shown in title block; Address3: Not shown in title block; Address4: Not shown in title block; DocumentNumber: 8; Revision: Use project parameter SCH_Rev; SheetNumber: 8; SheetTotal: 8; PageSetup: Record=PageOptions¦CenterHorizontal=True¦CenterVertical=True¦PrintScale=1.00¦XCorrection=1.00¦YCorrection=1.00¦PrintKind=0¦BorderSize=5000000¦LeftOffset=0¦BottomOffset=0¦Orientation=2¦PaperLength=1000¦PaperWidth=1000¦Scale=100¦PaperSource=15¦PrintQuality=600¦MediaType=1¦DitherType=10¦PaperKind=Letter¦PrintScaleMode=1
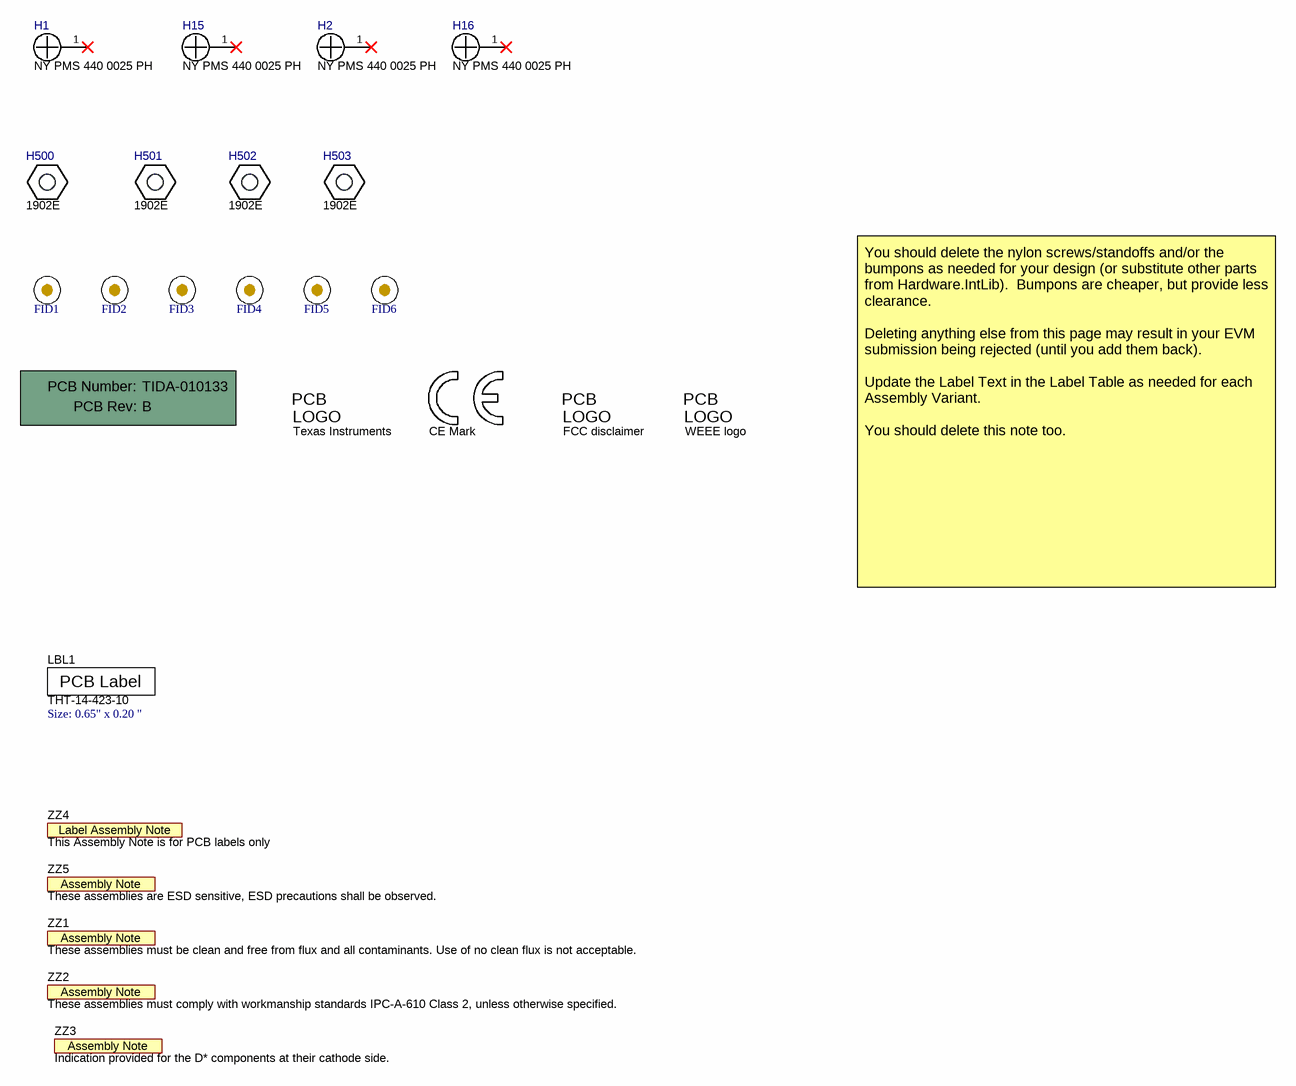
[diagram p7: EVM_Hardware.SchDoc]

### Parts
!PCB1  Printed Circuit Board  (value not drawn)  (mechanical)
FID1  Fiducial  [Fiducial10-20]  (value not drawn)
FID2  Fiducial  [Fiducial10-20]  (value not drawn)
FID3  Fiducial  [Fiducial10-20]  (value not drawn)
FID4  Fiducial  [Fiducial10-20]  (value not drawn)
FID5  Fiducial  [Fiducial10-20]  (value not drawn)
FID6  Fiducial  [Fiducial10-20]  (value not drawn)
H1  NY PMS 440 0025 PH  [NY PMS 440 0025 PH]
H2  NY PMS 440 0025 PH  [NY PMS 440 0025 PH]
H15  NY PMS 440 0025 PH  [NY PMS 440 0025 PH]
H16  NY PMS 440 0025 PH  [NY PMS 440 0025 PH]
H500  1902E  [Keystone_1902E]
H501  1902E  [Keystone_1902E]
H502  1902E  [Keystone_1902E]
H503  1902E  [Keystone_1902E]
LBL1  THT-14-423-10  Note: Size: 0.65" x 0.20 "  [Label_650x200]
Logo1  CE Mark  [CE_Mark_5mm]  (no BOM)
Logo2  FCC disclaimer  [FCC_disclaimer]  (no BOM)
Logo3  WEEE logo  [WEEE_Minimum]  (no BOM)
Logo4  Texas Instruments  [TI_Stacked_Overlay_Small]  (no BOM)
ZZ1  These assemblies must be clean and free from flux and all contaminants. Use of no clean flux is not acceptable.  [AssemblyNote]  (no BOM)
ZZ2  These assemblies must comply with workmanship standards IPC-A-610 Class 2, unless otherwise specified.  [AssemblyNote]  (no BOM)
ZZ3  Indication provided for the D* components at their cathode side.  [AssemblyNote]  (no BOM)
ZZ4  This Assembly Note is for PCB labels only  [AssemblyNoteLabel]  (no BOM)
ZZ5  These assemblies are ESD sensitive, ESD precautions shall be observed.  [AssemblyNote]  (no BOM)

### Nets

Not connected (* = marked no-connect by the designer): H1 1*; H2 1*; H15 1*; H16 1*

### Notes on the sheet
- You should delete the nylon screws/standoffs and/or the bumpons as needed for your design (or substitute other parts from Hardware.IntLib).  Bumpons are cheaper, but provide less clearance.
  Deleting anything else from this page may result in your EVM submission being rejected (until you add them back).
  Update the Label Text in the Label Table as needed for each Assembly Variant.
  You should delete this note too.

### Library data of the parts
!PCB1 = CMP-0003618-2: Manufacturer: Any; PartNumber: TIDA-010133
FID1-FID6 = CMP-0077181-1: Fiducial mark.  There is nothing to buy or mount.
H1 H2 H15 H16 = CMP-0003617-1: Machine Screw, Round, #4-40 x 1/4, Nylon, Philips panhead; Manufacturer: B&F Fastener Supply; CompType: Hardware
H500-H503 = CMP-0003611-1: Standoff, Hex, 1"L #4-40 Nylon; Manufacturer: Keystone; CompType: Hardware
LBL1 = CMP-0003625-1: Thermal Transfer Printable Labels, 0.650" W x 0.200" H - 10,000 per roll; Manufacturer: Brady
Logo1 = CMP-0074844-2: Manufacturer: Texas Instruments; SymbolCreator: a0412235; AEC Category: Q200; CompType: IC
Logo2 = CMP-0074847-1: FCC_disclaimer
Logo3 = CMP-0074769-4: Manufacturer: Texas Instruments; AEC Category: Q200; CompType: IC
Logo4 = CMP-0074838-1: Texas Instrument Corporate Signature; SymbolCreator: a0412235; Lib Reference: TI_Logo
ZZ1 = CMP-0077237-1
ZZ2 = CMP-0077238-1
ZZ3 = CMP-0077238-1: These assemblies must comply with workmanship standards IPC-A-610 Class 2, unless otherwise specified.
ZZ4 = CMP-0003616-3
ZZ5 = CMP-0077236-1

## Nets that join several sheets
+2.5VA: 3_BUF802_OFFSET_TRIGGER (L512.1), 5_BUF802_PWR_PG1 (7 pins), 6_BUF802_PWR_PG2 (U28.24)
+2.5VA_1: 3_BUF802_OFFSET_TRIGGER (10 pins), 4_BUF802_USBIF (R93.2 R95.2 U11.2)
+3P3VD: 1_BUF802_CH1_AFE (L13.1 L500.2 R147.1), 2_BUF802_CH2_AFE (L14.1 L501.2 R148.1), 3_BUF802_OFFSET_TRIGGER (C530.1 L509.1), 4_BUF802_USBIF (36 pins), 5_BUF802_PWR_PG1 (7 pins)
+5VA: 1_BUF802_CH1_AFE (L9.2 L11.1 L502.1 R43.2), 2_BUF802_CH2_AFE (L10.2 L12.2 L503.1 R45.2), 3_BUF802_OFFSET_TRIGGER (5 pins), 5_BUF802_PWR_PG1 (TP3.1), 6_BUF802_PWR_PG2 (R101.2 R114.2 R167.2)
+8VA: 1_BUF802_CH1_AFE (C1.1 L514.2), 2_BUF802_CH2_AFE (C2.1 L513.2), 5_BUF802_PWR_PG1 (5 pins)
+12VA: 5_BUF802_PWR_PG1 (13 pins), 6_BUF802_PWR_PG2 (C104.2 C109.1 U28.18 U28.23)
-2.5VA: 3_BUF802_OFFSET_TRIGGER (L511.2), 5_BUF802_PWR_PG1 (6 pins)
-3.3VA: 1_BUF802_CH1_AFE (C551.2 L7.1), 2_BUF802_CH2_AFE (C552.2 L8.1), 5_BUF802_PWR_PG1 (5 pins)
-5VA: 1_BUF802_CH1_AFE (L3.2), 2_BUF802_CH2_AFE (L4.2), 3_BUF802_OFFSET_TRIGGER (C546.1 L510.1), 5_BUF802_PWR_PG1 (C78.1 TP6.1 U16.5), 6_BUF802_PWR_PG2 (6 pins)
GND: 1_BUF802_CH1_AFE (82 pins), 2_BUF802_CH2_AFE (82 pins), 3_BUF802_OFFSET_TRIGGER (71 pins), 4_BUF802_USBIF (69 pins), 5_BUF802_PWR_PG1 (68 pins), 6_BUF802_PWR_PG2 (74 pins)
CH1_ACDC_GAINADJ: 1_BUF802_CH1_AFE (R10.2), 3_BUF802_OFFSET_TRIGGER (R548.1 U507.1)
CH1_CALIB: 1_BUF802_CH1_AFE (J3.2), 3_BUF802_OFFSET_TRIGGER (C526.1 R523.2)
CH1_HYSIS: 1_BUF802_CH1_AFE (R154.2), 3_BUF802_OFFSET_TRIGGER (R555.2 U507.4)
CH1_OFFSET: 1_BUF802_CH1_AFE (R32.2), 3_BUF802_OFFSET_TRIGGER (C564.1 R541.2)
CH1_TRIG_REF: 1_BUF802_CH1_AFE (R143.1), 3_BUF802_OFFSET_TRIGGER (C500.1 R500.2)
CH2_ACDC_GAINADJ: 2_BUF802_CH2_AFE (R9.2), 3_BUF802_OFFSET_TRIGGER (R508.1 U502.1)
CH2_CALIB: 2_BUF802_CH2_AFE (J4.2), 3_BUF802_OFFSET_TRIGGER (C523.1 R518.2)
CH2_HYSIS: 2_BUF802_CH2_AFE (R155.2), 3_BUF802_OFFSET_TRIGGER (R511.2 U502.4)
CH2_OFFSET: 2_BUF802_CH2_AFE (R33.2), 3_BUF802_OFFSET_TRIGGER (C557.1 R535.2)
CH2_TRIG_REF: 2_BUF802_CH2_AFE (R145.1), 3_BUF802_OFFSET_TRIGGER (C501.1 R501.2)
DAC_CS0: 3_BUF802_OFFSET_TRIGGER (U24.12), 4_BUF802_USBIF (U9.12)
DAC_SCLK: 3_BUF802_OFFSET_TRIGGER (U24.13), 4_BUF802_USBIF (U9.4)
DAC_SDI: 3_BUF802_OFFSET_TRIGGER (U24.14), 4_BUF802_USBIF (U9.7)
DAC_SDO_ALARM: 3_BUF802_OFFSET_TRIGGER (U24.15), 4_BUF802_USBIF (U9.9)
LMH6518_SCK: 1_BUF802_CH1_AFE (U7.11), 2_BUF802_CH2_AFE (U8.11), 4_BUF802_USBIF (U14.4)
LMH6518_SCS0: 1_BUF802_CH1_AFE (U7.9), 4_BUF802_USBIF (U14.9)
LMH6518_SCS1: 2_BUF802_CH2_AFE (U8.9), 4_BUF802_USBIF (U14.12)
LMH6518_SDIO: 1_BUF802_CH1_AFE (U7.10), 2_BUF802_CH2_AFE (U8.10), 4_BUF802_USBIF (U14.7)
SMB_CLK: 3_BUF802_OFFSET_TRIGGER (R528.1 U502.10 U507.10), 4_BUF802_USBIF (R95.1 U11.4)
SMB_DAT: 3_BUF802_OFFSET_TRIGGER (R527.1 U502.9 U507.9), 4_BUF802_USBIF (R93.1 U11.3)

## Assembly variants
TIDA_010133: not fitted C527 C533 C553 C558 FID1 FID2 FID3 FID4 FID5 FID6 R78 R88 R92 R113 R118 R121 R122 R125 R149 R150 R508 R511 R532 R548 R553 R555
